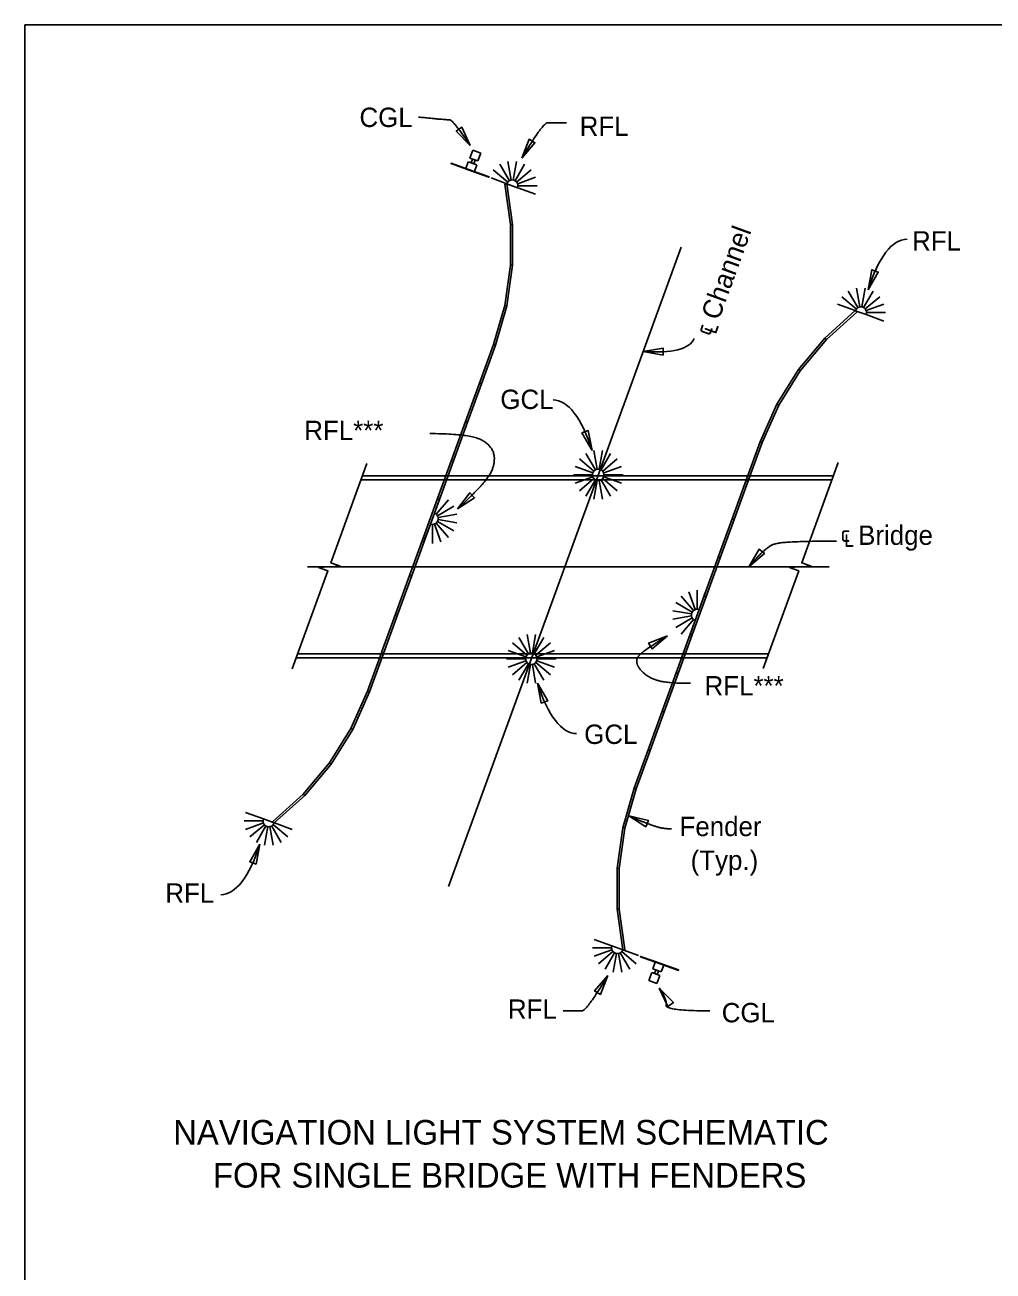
# Model space of a CAD drawing. Extents: x 0 to 1539, y 0 to 973.
# Drawn here: x 0 to 378.1, y 486.5 to 973 of the extents above; entities that cross this region are included whole.
import ezdxf

# ---------------------------------------------------------------- set-up
doc = ezdxf.new("R2010")
doc.units = 0
for name, color, linetype in [('Dimension', 7, 'Continuous'), ('Miscellaneous', 7, 'Continuous'), ('Miscellaneous1', 7, 'Continuous'), ('NavLight', 7, 'Continuous'), ('SupstrConc', 7, 'Continuous'), ('TextStructures', 7, 'Continuous'), ('Wood', 7, 'Continuous')]:
    doc.layers.add(name, color=color, linetype=linetype)

msp = doc.modelspace()

# ---------------------------------------------------------------- linework, layer by layer
at = {"layer": 'Dimension'}
for points in [[(0, 0), (1539.4, 0), (1539.4, 972.98), (0, 972.98)], [(173.97, 925.89), (170.61, 933.06), (168.44, 931.55)], [(194.03, 921), (199.22, 926.99), (196.96, 928.36)], [(329.33, 869.59), (333.26, 876.46), (330.77, 877.37)], [(241.49, 845.55), (249.27, 844.08), (249.32, 846.73)], [(221.52, 806.84), (220.04, 814.62), (217.56, 813.7)], [(169, 784.01), (175.6, 788.39), (173.78, 790.32)], [(282.78, 761.44), (288.8, 766.58), (286.77, 768.28)], [(251.01, 734.44), (243.6, 731.65), (244.93, 729.36)], [(200.23, 716.03), (201.7, 708.25), (204.18, 709.17)], [(235.84, 664.22), (242.5, 659.93), (243.54, 662.36)], [(91.74, 653.16), (87.81, 646.28), (90.3, 645.37)], [(227.71, 601.87), (222.52, 595.88), (224.78, 594.51)], [(247.77, 596.99), (251.13, 589.81), (253.3, 591.32)]]:
    msp.add_lwpolyline(points, close=True, dxfattribs=at)
for points in [[(104.44, 721.62), (118.35, 759.85), (114.71, 761.18), (118.93, 761.44), (123.15, 761.7), (119.51, 763.02), (133.59, 801.71)], [(288.37, 721.77), (302.24, 759.85), (298.59, 761.18), (302.81, 761.44), (307.03, 761.7), (303.39, 763.02), (317.62, 802.12)]]:
    msp.add_lwpolyline(points, dxfattribs=at)
for centre, major_axis, ratio, start_param, end_param in [((343.66, 832.04), (-0.91, -57.27), 0.343516, 3.141594, 4.002916), ((196.41, 876.57), (-65, 26.05), 0.265294, 2.43766, 3.141592), ((207.18, 769.3), (0.91, -57.27), 0.343516, 2.28027, 3.141592), ((214.56, 753.58), (-0.91, 57.27), 0.343516, 2.28027, 3.141592), ((77.41, 690.7), (0.91, 57.27), 0.343516, 3.141594, 4.002916)]:
    msp.add_ellipse(centre, major_axis=major_axis, ratio=ratio, start_param=start_param, end_param=end_param, dxfattribs=at)
for points in [[(173.97, 925.89), (167.13, 935.96), (164.78, 935.88), (153.79, 937.01)], [(211.48, 934.78), (205.72, 934.78), (202.41, 934.78), (194.03, 921)], [(158.18, 813.43), (174.35, 813.43), (183.35, 807.96), (183.35, 799.45), (177.15, 791.67), (169, 784.01)], [(282.78, 761.44), (289.31, 769.41), (296.88, 771.45), (316.95, 771.45)], [(259.91, 715.95), (251.54, 715.95), (243.86, 717.87), (238.54, 723.01), (239.5, 727.73), (251.01, 734.44)], [(252.57, 659.13), (249.18, 659.13), (242.97, 661.17), (235.84, 664.22)], [(210.26, 588.09), (216.02, 588.09), (219.34, 588.09), (227.71, 601.87)], [(247.77, 596.99), (250.91, 592.45), (250.04, 588.09), (267.48, 588.09)]]:
    msp.add_open_spline(points, degree=2, dxfattribs=at)
at = {"layer": 'Miscellaneous'}
for p, q in [((210.87, 761.44), (256.28, 886.2)), ((110.4, 761.44), (210.87, 761.44)), ((165.46, 636.67), (210.87, 761.44)), ((210.87, 761.44), (314.18, 761.44))]:
    msp.add_line(p, q, dxfattribs=at)
at = {"layer": 'Miscellaneous1'}
msp.add_lwpolyline([(0, 972.98), (1539.4, 972.98), (1539.4, 0), (0, 0)], close=True, dxfattribs=at)
at = {"layer": 'NavLight'}
for p, q in [((172.23, 916.95), (173.18, 919.59)), ((176.53, 918.39), (173.18, 919.59)), ((174.93, 924.05), (173.83, 920.98)), ((176.91, 919.88), (173.83, 920.98)), ((174.32, 919.18), (174.84, 920.62)), ((178.01, 922.94), (174.93, 924.05)), ((175.38, 918.8), (175.9, 920.24)), ((178.01, 922.94), (176.91, 919.88)), ((189.95, 912.42), (188.66, 919.71)), ((190.73, 912.42), (192.01, 919.71)), ((175.58, 915.74), (176.53, 918.39)), ((188.61, 911.65), (182.94, 916.41)), ((189.21, 912.15), (185.51, 918.56)), ((191.46, 912.15), (195.16, 918.56)), ((192.06, 911.65), (197.73, 916.41)), ((188.22, 910.97), (182.05, 913.22)), ((192.45, 909.42), (188.22, 910.97)), ((192.49, 910.97), (199.44, 913.5)), ((192.62, 910.19), (200.02, 910.19)), ((192.48, 909.41), (199.43, 906.88)), ((324.7, 862.12), (319.03, 866.88)), ((325.3, 862.63), (321.6, 869.04)), ((326.06, 862.88), (324.78, 870.17)), ((326.85, 862.88), (328.13, 870.17)), ((327.58, 862.61), (331.28, 869.02)), ((328.18, 862.11), (333.85, 866.87)), ((324.31, 861.43), (317.35, 863.96)), ((324.34, 861.42), (328.57, 859.89)), ((328.57, 861.43), (335.53, 863.96)), ((328.57, 859.89), (335.53, 857.36)), ((328.71, 860.66), (336.11, 860.66)), ((222.22, 798.8), (216.55, 803.56)), ((222.82, 799.3), (219.12, 805.71)), ((223.55, 799.57), (222.27, 806.86)), ((224.33, 799.57), (225.62, 806.86)), ((225.07, 799.3), (228.77, 805.71)), ((225.7, 798.81), (231.37, 803.57)), ((221.83, 798.12), (214.87, 800.65)), ((226.09, 798.12), (233.05, 800.65)), ((221.69, 797.35), (214.29, 797.35)), ((221.83, 796.58), (214.87, 794.05)), ((222.22, 795.91), (216.55, 791.15)), ((222.82, 795.4), (219.12, 788.99)), ((223.55, 795.14), (222.27, 787.85)), ((224.33, 795.14), (225.62, 787.85)), ((225.07, 795.4), (228.77, 788.99)), ((225.7, 795.9), (231.37, 791.14)), ((226.09, 796.59), (233.05, 794.06)), ((226.23, 797.37), (233.63, 797.37)), ((159.96, 782.36), (162.49, 789.32)), ((160.63, 781.97), (165.39, 787.64)), ((161.14, 781.37), (167.55, 785.07)), ((158.4, 778.14), (159.96, 782.36)), ((160.63, 778.52), (165.39, 772.85)), ((161.14, 779.12), (167.55, 775.42)), ((161.4, 780.64), (168.69, 781.92)), ((161.4, 779.86), (168.69, 778.57)), ((158.39, 778.11), (155.86, 771.15)), ((159.17, 777.97), (159.17, 770.56)), ((159.95, 778.1), (162.49, 771.14)), ((261.11, 744.35), (256.35, 750.02)), ((261.78, 744.74), (259.25, 751.7)), ((262.55, 744.88), (262.55, 752.28)), ((263.32, 744.74), (265.86, 751.7)), ((260.6, 743.75), (254.19, 747.45)), ((261.8, 740.51), (263.32, 744.74)), ((260.34, 743.02), (253.05, 744.3)), ((260.34, 742.23), (253.05, 740.95)), ((260.59, 741.47), (254.17, 737.77)), ((261.1, 740.87), (256.34, 735.2)), ((261.79, 740.48), (259.26, 733.52)), ((197.41, 727.74), (196.12, 735.03)), ((198.19, 727.74), (199.47, 735.03)), ((196.07, 726.97), (190.4, 731.72)), ((196.67, 727.47), (192.97, 733.88)), ((198.92, 727.47), (202.62, 733.88)), ((199.56, 726.97), (205.23, 731.73)), ((195.55, 725.52), (188.15, 725.52)), ((195.68, 726.29), (188.73, 728.82)), ((199.95, 726.29), (206.9, 728.82)), ((200.08, 725.54), (207.48, 725.54)), ((195.68, 724.75), (188.73, 722.22)), ((196.07, 724.07), (190.4, 719.32)), ((196.67, 723.57), (192.97, 717.16)), ((197.41, 723.3), (196.12, 716.01)), ((198.19, 723.3), (199.47, 716.01)), ((198.92, 723.57), (202.62, 717.16)), ((199.56, 724.06), (205.23, 719.31)), ((199.95, 724.75), (206.9, 722.22)), ((93.04, 662.21), (85.63, 662.21)), ((93.17, 662.98), (86.22, 665.51)), ((97.41, 661.46), (93.17, 662.98)), ((93.17, 661.44), (86.22, 658.91)), ((93.56, 660.76), (87.89, 656.01)), ((94.16, 660.26), (90.46, 653.85)), ((94.9, 660), (93.61, 652.71)), ((95.68, 660), (96.96, 652.71)), ((96.44, 660.24), (100.14, 653.83)), ((97.04, 660.76), (102.71, 656)), ((97.44, 661.45), (104.39, 658.91)), ((229.26, 613.46), (222.31, 616)), ((229.29, 613.45), (233.52, 611.9)), ((229.12, 612.68), (221.72, 612.68)), ((229.25, 611.9), (222.3, 609.37)), ((229.68, 611.22), (224.01, 606.46)), ((230.28, 610.72), (226.58, 604.31)), ((231.01, 610.45), (229.73, 603.16)), ((231.79, 610.45), (233.08, 603.16)), ((232.53, 610.72), (236.23, 604.31)), ((233.13, 611.22), (238.8, 606.46)), ((233.52, 611.9), (239.69, 609.65)), ((246.16, 607.13), (245.21, 604.48)), ((245.21, 604.48), (248.56, 603.28)), ((246.36, 604.07), (245.84, 602.63)), ((247.42, 603.69), (246.9, 602.25)), ((249.51, 605.93), (248.56, 603.28)), ((243.73, 599.93), (244.83, 603)), ((243.73, 599.93), (246.82, 598.82)), ((244.83, 603), (247.92, 601.89)), ((246.82, 598.82), (247.92, 601.89))]:
    msp.add_line(p, q, dxfattribs=at)
for centre in [(223.94, 797.35), (197.8, 725.52)]:
    msp.add_circle(centre, 2.25, dxfattribs=at)
for centre, start, end in [((190.34, 910.2), 339.6086, 160), ((326.46, 860.66), 340, 160.3914), ((159.19, 780.25), 249.6086, 70), ((262.55, 742.63), 70, 250.3914), ((95.29, 662.21), 160, 340.3914), ((231.4, 612.67), 159.6086, 340)]:
    msp.add_arc(centre, 2.25, start, end, dxfattribs=at)
at = {"layer": 'SupstrConc'}
for p, q in [((131.3, 795.44), (315.19, 795.44)), ((131.87, 796.98), (315.75, 796.98)), ((105.99, 725.89), (289.88, 725.89)), ((106.55, 727.44), (290.44, 727.44))]:
    msp.add_line(p, q, dxfattribs=at)
at = {"layer": 'Wood'}
for p, q in [((188.22, 910.97), (187.4, 910.86)), ((189.62, 895.07), (187.4, 910.86)), ((190.45, 895.13), (188.22, 910.97)), ((189.62, 895.07), (190.45, 895.13)), ((189.62, 879.19), (189.62, 895.07)), ((190.45, 879.13), (190.45, 895.13)), ((187.41, 863.46), (189.62, 879.19)), ((188.22, 863.29), (190.45, 879.13)), ((189.62, 879.19), (190.45, 879.13)), ((183.02, 848.16), (187.41, 863.46)), ((183.81, 847.91), (188.22, 863.29)), ((187.41, 863.46), (188.22, 863.29)), ((312.45, 850.73), (324.34, 861.43)), ((324.34, 861.43), (324.9, 860.81)), ((313.05, 850.15), (324.9, 860.81)), ((177.56, 833.16), (183.02, 848.16)), ((178.34, 832.87), (183.81, 847.91)), ((183.02, 848.16), (183.81, 847.91)), ((302.17, 838.47), (312.45, 850.73)), ((302.84, 837.98), (313.05, 850.15)), ((313.05, 850.15), (312.45, 850.73)), ((293.69, 824.9), (302.17, 838.47)), ((294.42, 824.51), (302.84, 837.98)), ((302.84, 837.98), (302.17, 838.47)), ((172.09, 818.12), (177.56, 833.16)), ((172.87, 817.84), (178.34, 832.87)), ((178.34, 832.87), (177.56, 833.16)), ((287.18, 810.28), (293.69, 824.9)), ((287.95, 809.97), (294.42, 824.51)), ((294.42, 824.51), (293.69, 824.9)), ((166.61, 803.09), (172.09, 818.12)), ((167.4, 802.8), (172.87, 817.84)), ((172.87, 817.84), (172.09, 818.12)), ((281.71, 795.25), (287.18, 810.28)), ((282.49, 794.96), (287.95, 809.97)), ((287.95, 809.97), (287.18, 810.28)), ((166.61, 803.09), (161.14, 788.05)), ((167.4, 802.8), (161.92, 787.77)), ((167.4, 802.8), (166.61, 803.09)), ((276.23, 780.21), (281.71, 795.25)), ((277.02, 779.93), (282.49, 794.96)), ((281.71, 795.25), (282.49, 794.96)), ((155.67, 773.02), (161.14, 788.05)), ((161.92, 787.77), (156.45, 772.73)), ((161.92, 787.77), (161.14, 788.05)), ((270.76, 765.18), (276.23, 780.21)), ((271.55, 764.89), (277.02, 779.93)), ((276.23, 780.21), (277.02, 779.93)), ((155.67, 773.02), (150.2, 757.98)), ((156.45, 772.73), (150.98, 757.7)), ((156.45, 772.73), (155.67, 773.02)), ((270.76, 765.18), (265.29, 750.14)), ((271.55, 764.89), (266.07, 749.86)), ((270.76, 765.18), (271.55, 764.89)), ((150.2, 757.98), (144.73, 742.97)), ((150.98, 757.7), (145.51, 742.66)), ((150.98, 757.7), (150.2, 757.98)), ((265.29, 750.14), (259.82, 735.11)), ((260.6, 734.82), (266.07, 749.86)), ((265.29, 750.14), (266.07, 749.86)), ((144.72, 742.94), (139.26, 727.94)), ((145.51, 742.66), (140.03, 727.62)), ((145.51, 742.66), (144.72, 742.94)), ((259.82, 735.11), (254.35, 720.07)), ((260.6, 734.82), (255.13, 719.79)), ((259.82, 735.11), (260.6, 734.82)), ((139.25, 727.91), (133.79, 712.9)), ((140.03, 727.62), (134.56, 712.59)), ((140.03, 727.62), (139.25, 727.91)), ((254.35, 720.07), (248.87, 705.04)), ((254.35, 720.07), (255.13, 719.79)), ((255.13, 719.79), (249.67, 704.78)), ((133.79, 712.9), (127.32, 698.37)), ((134.56, 712.59), (128.05, 697.97)), ((133.79, 712.9), (134.56, 712.59)), ((248.87, 705.04), (243.4, 690)), ((249.66, 704.75), (244.19, 689.74)), ((248.87, 705.04), (249.66, 704.75)), ((127.32, 698.37), (118.9, 684.9)), ((128.05, 697.97), (119.58, 684.4)), ((127.32, 698.37), (128.05, 697.97)), ((243.4, 690), (237.93, 674.97)), ((244.18, 689.72), (238.72, 674.71)), ((243.4, 690), (244.18, 689.72)), ((118.9, 684.9), (108.69, 672.73)), ((119.58, 684.4), (109.29, 672.15)), ((118.9, 684.9), (119.58, 684.4)), ((108.69, 672.73), (96.84, 662.06)), ((109.29, 672.15), (97.4, 661.44)), ((108.69, 672.73), (109.29, 672.15)), ((237.93, 674.97), (233.52, 659.59)), ((238.72, 674.71), (234.34, 659.41)), ((238.72, 674.71), (237.93, 674.97)), ((97.4, 661.44), (96.84, 662.06)), ((233.52, 659.59), (231.29, 643.74)), ((234.34, 659.41), (232.12, 643.68)), ((234.34, 659.41), (233.52, 659.59)), ((231.29, 643.74), (231.29, 627.74)), ((232.12, 643.68), (231.29, 643.74)), ((232.12, 643.68), (232.12, 627.8)), ((232.12, 627.8), (231.29, 627.74)), ((231.29, 627.74), (233.52, 611.9)), ((232.12, 627.8), (234.34, 612.01)), ((233.52, 611.9), (234.34, 612.01))]:
    msp.add_line(p, q, dxfattribs=at)
for points in [[(175.96, 915.41), (166.43, 918.83), (166.49, 919), (171.79, 917.1)], [(171.79, 917.1), (181.32, 913.69), (181.25, 913.51), (175.96, 915.41)], [(249.95, 605.77), (240.42, 609.19), (240.49, 609.36), (245.78, 607.46)], [(245.78, 607.46), (255.31, 604.05), (255.25, 603.87), (249.95, 605.77)]]:
    msp.add_lwpolyline(points, dxfattribs=at)

# ---------------------------------------------------------------- texts
at = {"layer": 'Dimension'}
for s, height, p in [('Fender', 7.56, (255.68, 656.3)), ('(Typ.)', 7.56, (260.02, 643.1)), ('NAVIGATION LIGHT SYSTEM SCHEMATIC', 9.6, (57.9, 535.88)), ('FOR SINGLE BRIDGE WITH FENDERS', 9.6, (73.42, 519.08))]:
    msp.add_text(s, height=height, dxfattribs=at).set_placement(p)
at = {"layer": 'TextStructures'}
for s, p in [('CGL', (130.67, 933.13)), ('RFL', (216.68, 929.64)), ('RFL', (346.51, 884.9)), ('GCL', (185.69, 823.04)), ('RFL***', (109.12, 810.89)), ('℄ Bridge ', (318.53, 769.99)), ('RFL***', (265.45, 711.21)), ('GCL', (218.44, 692.28)), ('RFL', (54.85, 630.29)), ('RFL', (188.65, 584.97)), ('CGL', (272.16, 583.6))]:
    msp.add_text(s, height=7.56, dxfattribs=at).set_placement(p)
msp.add_text('℄ Channel', height=7.56, rotation=70, dxfattribs=at).set_placement((268.64, 850.81))

doc.saveas('drawing.dxf')
